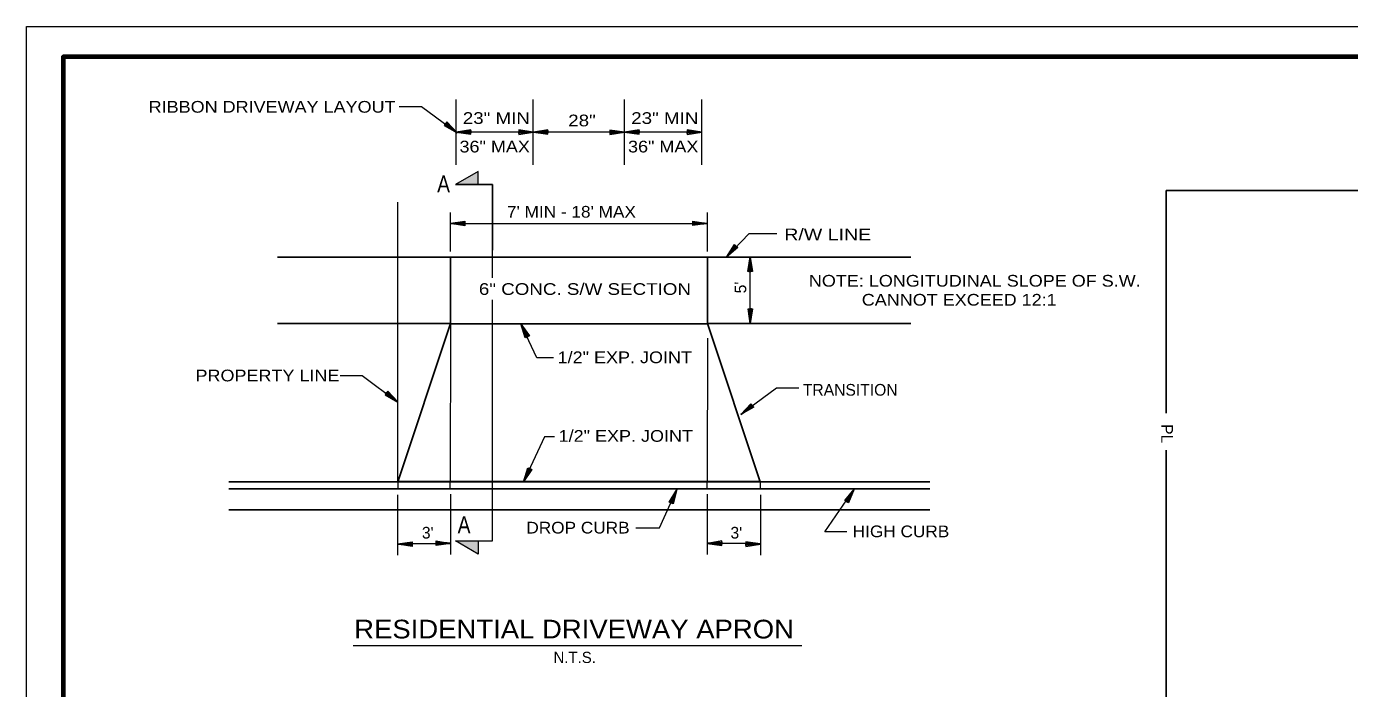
# Model space of a CAD drawing. Extents: x 124.7 to 141.7, y -6.7 to 4.3.
# Drawn here: x 124.66 to 134.08, y -0.42 to 4.3 of the extents above; entities that cross this region are included whole.
import ezdxf

# ---------------------------------------------------------------- set-up
doc = ezdxf.new("R2010")
doc.units = 0
doc.header["$LTSCALE"] = 0.033
for name, color, linetype, lineweight in [('1', 7, 'Continuous', 13), ('6', 7, 'Continuous', 13), ('60', 7, 'Continuous', 13), ('7', 7, 'Continuous', 13), ('8', 7, 'Continuous', 13)]:
    doc.layers.add(name, color=color, linetype=linetype, lineweight=lineweight)

msp = doc.modelspace()

# ---------------------------------------------------------------- hatches: boundary and pattern name
at = {"layer": '6'}
for points in [[(127.712, 3.17258), (127.87396, 3.17258), (127.87396, 3.26548)], [(127.712, 0.63499), (127.87396, 0.63499), (127.87396, 0.54209)]]:
    msp.add_hatch(color=256, dxfattribs=at).paths.add_polyline_path(points)

# ---------------------------------------------------------------- linework, layer by layer
at = {"layer": '1'}
for p, q in [((127.71735, 3.3141), (127.71735, 3.77832)), ((128.26735, 3.3141), (128.26735, 3.77832)), ((128.91735, 3.3141), (128.91735, 3.77832)), ((129.46735, 3.3141), (129.46735, 3.77832)), ((129.46735, 3.54622), (127.71735, 3.54622)), ((127.30268, 1.06025), (127.30268, 3.04831)), ((127.30128, 1.05608), (127.30128, 1.00608)), ((129.88319, 1.05608), (129.88319, 1.00608))]:
    msp.add_line(p, q, dxfattribs=at)
at = {"layer": '6', "lineweight": 25}
for p, q in [((132.77677, 1.54519), (132.77677, 3.13027)), ((132.77677, 3.13027), (136.71186, 3.13027)), ((126.44573, 2.65608), (127.67721, 2.65608)), ((127.67721, 2.65608), (127.67721, 2.18432)), ((129.50727, 2.18432), (129.50727, 2.65608)), ((126.44573, 2.18432), (127.67721, 2.18432)), ((127.67721, 2.18016), (129.50727, 2.18016)), ((129.50727, 2.18432), (130.95673, 2.18432)), ((132.77677, -2.5979), (132.77677, 1.28283)), ((126.09806, 1.05608), (131.09128, 1.05608)), ((126.09806, 1.00608), (131.09128, 1.00608)), ((126.09806, 0.85608), (131.09128, 0.85608))]:
    msp.add_line(p, q, dxfattribs=at)
at = {"layer": '6'}
for p, q in [((127.67721, 2.69545), (127.67721, 2.97502)), ((129.50727, 2.69545), (129.50727, 2.97502)), ((127.67721, 2.89628), (129.50727, 2.89628)), ((129.81224, 2.18432), (129.81224, 2.65608)), ((127.30268, 1.06025), (129.8818, 1.06025)), ((127.6752, 1.00608), (127.67519, 1.05608)), ((129.50643, 1.00608), (129.50643, 1.05608)), ((127.29968, 0.96297), (127.29968, 0.53424)), ((127.67805, 0.96822), (127.67805, 0.53949)), ((129.50643, 0.96822), (129.50643, 0.53949)), ((129.8848, 0.96297), (129.8848, 0.53424)), ((127.33965, 0.61823), (127.67805, 0.61823)), ((129.84483, 0.61823), (129.50643, 0.61823))]:
    msp.add_line(p, q, dxfattribs=at)
for points in [[(127.31231, 3.72973), (127.46994, 3.72973), (127.72372, 3.54149)], [(127.712, 3.17258), (127.97628, 3.17258), (127.97628, 2.70471)], [(127.97628, 2.50923), (127.97628, 3.17258), (127.712, 3.17258)], [(130.00182, 2.82196), (129.80183, 2.82196), (129.64364, 2.65608)], [(127.712, 0.63499), (127.97628, 0.63499), (127.97628, 2.35086)], [(128.41153, 1.93962), (128.29359, 1.93962), (128.17884, 2.18016)], [(126.89127, 1.81282), (127.0489, 1.81282), (127.30268, 1.62458)], [(130.15782, 1.72359), (130.0002, 1.72359), (129.74642, 1.53535)], [(128.41861, 1.37609), (128.34805, 1.37609), (128.19752, 1.05608)], [(127.712, 0.63499), (127.97628, 0.63499), (127.97628, 1.10286)], [(128.99752, 0.72783), (129.1658, 0.72783), (129.29008, 1.00143)], [(130.50201, 0.70041), (130.34439, 0.70041), (130.5535, 1.00372)]]:
    msp.add_lwpolyline(points, dxfattribs=at)
for points in [[(127.712, 3.17258), (127.87396, 3.17258), (127.87396, 3.26548)], [(127.712, 0.63499), (127.87396, 0.63499), (127.87396, 0.54209)]]:
    msp.add_lwpolyline(points, close=True, dxfattribs=at)
at = {"layer": '6', "lineweight": 25}
msp.add_lwpolyline([(127.67721, 2.65608), (129.50727, 2.65608), (130.95673, 2.65608)], dxfattribs=at)
at = {"layer": '60'}
msp.add_lwpolyline([(141.66697, -6.70846), (124.65648, -6.70846), (124.65648, 4.29833), (141.66697, 4.29833)], close=True, dxfattribs=at)
at = {"layer": '60', "lineweight": 70}
msp.add_lwpolyline([(140.98583, 4.08146), (124.91782, 4.08146), (124.91782, -6.47409), (140.98583, -6.47409)], close=True, dxfattribs=at)
at = {"layer": '7'}
msp.add_line((126.98512, -0.10881), (130.17964, -0.10881), dxfattribs=at)
at = {"layer": '8', "lineweight": 25}
for p, q in [((127.67721, 2.18432), (127.30128, 1.05608)), ((129.50727, 2.18432), (129.88319, 1.05608))]:
    msp.add_line(p, q, dxfattribs=at)
at = {"layer": '8'}
for p, q in [((127.67721, 2.18016), (127.67519, 1.05608)), ((129.5072, 2.07893), (129.50643, 1.05608))]:
    msp.add_line(p, q, dxfattribs=at)
for points in [[(127.72368, 3.542), (127.65216, 3.61857), (127.63196, 3.59345), (127.72374, 3.54149)], [(127.64898, 3.61451), (127.72366, 3.54115), (127.64246, 3.60639), (127.6392, 3.60232), (127.72366, 3.54115), (127.63594, 3.59827), (127.64572, 3.61045), (127.7196, 3.54441)], [(127.82152, 3.5358), (127.71735, 3.54622), (127.82152, 3.54622), (127.82152, 3.55143), (127.71735, 3.54622), (127.82152, 3.55664), (127.82152, 3.54101), (127.72256, 3.54622)], [(127.71787, 3.54554), (127.82159, 3.53065), (127.82159, 3.56289), (127.71751, 3.54591)], [(128.26683, 3.5469), (128.1631, 3.56179), (128.1631, 3.52955), (128.2672, 3.54653)], [(128.16319, 3.55664), (128.26735, 3.54622), (128.16319, 3.54622), (128.16319, 3.54101), (128.26735, 3.54622), (128.16319, 3.5358), (128.16319, 3.55143), (128.26215, 3.54622)], [(128.37152, 3.5358), (128.26735, 3.54622), (128.37152, 3.54622), (128.37152, 3.55143), (128.26735, 3.54622), (128.37152, 3.55664), (128.37152, 3.54101), (128.27256, 3.54622)], [(128.26788, 3.54554), (128.37159, 3.53065), (128.37159, 3.56289), (128.26751, 3.54591)], [(128.91735, 3.54622), (128.81363, 3.56111), (128.81363, 3.52887), (128.91772, 3.54585)], [(128.81371, 3.55596), (128.91788, 3.54554), (128.81371, 3.54554), (128.81371, 3.54033), (128.91788, 3.54554), (128.81371, 3.53512), (128.81371, 3.55075), (128.91267, 3.54554)], [(129.02152, 3.5358), (128.91735, 3.54622), (129.02152, 3.54622), (129.02152, 3.55143), (128.91735, 3.54622), (129.02152, 3.55664), (129.02152, 3.54101), (128.92256, 3.54622)], [(128.91788, 3.54554), (129.02159, 3.53065), (129.02159, 3.56289), (128.91751, 3.54591)], [(129.46683, 3.5469), (129.3631, 3.56179), (129.3631, 3.52955), (129.4672, 3.54653)], [(129.36319, 3.55664), (129.46735, 3.54622), (129.36319, 3.54622), (129.36319, 3.54101), (129.46735, 3.54622), (129.36319, 3.5358), (129.36319, 3.55143), (129.46215, 3.54622)], [(127.78007, 2.90654), (127.67591, 2.89613), (127.78007, 2.89613), (127.78007, 2.89092), (127.67591, 2.89613), (127.78007, 2.88571), (127.78007, 2.90133), (127.68111, 2.89613)], [(127.67643, 2.8968), (127.78015, 2.9117), (127.78015, 2.87946), (127.67606, 2.89644)], [(129.50805, 2.89576), (129.40432, 2.88086), (129.40432, 2.9131), (129.50842, 2.89613)], [(129.50805, 2.89576), (129.40432, 2.88086), (129.40432, 2.9131), (129.50842, 2.89613)], [(129.40441, 2.88602), (129.50857, 2.89644), (129.40441, 2.89644), (129.40441, 2.90165), (129.50857, 2.89644), (129.40441, 2.90685), (129.40441, 2.89123), (129.50336, 2.89644)], [(129.40441, 2.88602), (129.50857, 2.89644), (129.40441, 2.89644), (129.40441, 2.90165), (129.50857, 2.89644), (129.40441, 2.90685), (129.40441, 2.89123), (129.50336, 2.89644)], [(129.64347, 2.65693), (129.7004, 2.74491), (129.7247, 2.72372), (129.6435, 2.65642)], [(129.70423, 2.74146), (129.64364, 2.65609), (129.71208, 2.73461), (129.71601, 2.73119), (129.64364, 2.65609), (129.71994, 2.72777), (129.70816, 2.73803), (129.64705, 2.66002)], [(129.81276, 2.65686), (129.82766, 2.55314), (129.79542, 2.55314), (129.8124, 2.65723)], [(129.8225, 2.55322), (129.81208, 2.65739), (129.81208, 2.55322), (129.80687, 2.55322), (129.81208, 2.65739), (129.80167, 2.55322), (129.81729, 2.55322), (129.81208, 2.65218)], [(129.81172, 2.18354), (129.79682, 2.28726), (129.82906, 2.28726), (129.81208, 2.18318)], [(129.80198, 2.28719), (129.8124, 2.18302), (129.8124, 2.28719), (129.8176, 2.28719), (129.8124, 2.18302), (129.82281, 2.28719), (129.80719, 2.28719), (129.8124, 2.18823)], [(128.23454, 2.09307), (128.17811, 2.18125), (128.22526, 2.08835), (128.22061, 2.086), (128.17811, 2.18125), (128.21597, 2.08365), (128.2299, 2.09072), (128.18047, 2.1766)], [(128.17895, 2.18108), (128.23918, 2.09533), (128.21043, 2.08075), (128.17846, 2.18125)], [(127.30262, 1.62509), (127.2311, 1.70168), (127.21091, 1.67654), (127.30269, 1.62458)], [(127.22793, 1.6976), (127.30261, 1.62424), (127.22141, 1.68948), (127.21815, 1.68543), (127.30261, 1.62424), (127.21489, 1.68136), (127.22467, 1.69354), (127.29855, 1.6275)], [(129.74646, 1.53586), (129.81798, 1.61245), (129.83818, 1.58731), (129.7464, 1.53535)], [(129.82116, 1.60837), (129.74647, 1.53501), (129.82768, 1.60026), (129.83094, 1.5962), (129.74647, 1.53501), (129.8342, 1.59214), (129.82442, 1.60432), (129.75053, 1.53828)], [(128.19712, 1.05683), (128.2278, 1.15703), (128.25697, 1.14331), (128.1973, 1.05635)], [(128.23244, 1.15477), (128.19752, 1.05607), (128.24185, 1.15033), (128.24657, 1.14811), (128.19752, 1.05607), (128.25128, 1.14591), (128.23715, 1.15255), (128.19974, 1.06079)], [(129.2905, 1.00069), (129.26457, 0.89916), (129.23478, 0.9115), (129.29031, 1.00117)], [(129.25983, 0.90121), (129.29008, 1.00143), (129.25021, 0.9052), (129.2454, 0.90719), (129.29008, 1.00143), (129.24059, 0.90918), (129.25502, 0.9032), (129.28808, 0.99661)], [(130.55381, 1.00293), (130.51372, 0.90611), (130.48599, 0.92255), (130.55369, 1.00343)], [(130.50932, 0.9088), (130.55349, 1.00372), (130.50036, 0.91411), (130.49589, 0.91677), (130.55349, 1.00372), (130.49141, 0.91943), (130.50484, 0.91146), (130.55083, 0.99924)], [(127.40384, 0.6234), (127.29968, 0.61298), (127.40384, 0.61298), (127.40384, 0.60777), (127.29968, 0.61298), (127.40384, 0.60256), (127.40384, 0.61819), (127.30489, 0.61298)], [(127.3002, 0.61366), (127.40392, 0.62855), (127.40392, 0.59631), (127.29983, 0.61329)], [(127.67883, 0.61771), (127.5751, 0.60281), (127.5751, 0.63505), (127.6792, 0.61807)], [(127.57519, 0.60797), (127.67935, 0.61839), (127.57519, 0.61839), (127.57519, 0.62359), (127.67935, 0.61839), (127.57519, 0.6288), (127.57519, 0.61318), (127.67415, 0.61839)], [(129.60929, 0.60797), (129.50512, 0.61839), (129.60929, 0.61839), (129.60929, 0.62359), (129.50512, 0.61839), (129.60929, 0.6288), (129.60929, 0.61318), (129.51033, 0.61839)], [(129.50565, 0.61771), (129.60936, 0.60281), (129.60936, 0.63505), (129.50528, 0.61807)], [(129.88428, 0.61366), (129.78055, 0.62855), (129.78055, 0.59631), (129.88465, 0.61329)], [(129.78064, 0.6234), (129.8848, 0.61298), (129.78064, 0.61298), (129.78064, 0.60777), (129.8848, 0.61298), (129.78064, 0.60256), (129.78064, 0.61819), (129.87959, 0.61298)]]:
    msp.add_lwpolyline(points, dxfattribs=at)

# ---------------------------------------------------------------- texts
at = {"layer": '6'}
for s, height, width, p in [('RIBBON DRIVEWAY LAYOUT', 0.08333, 1.15, (125.5271, 3.68452)), ('23" MIN', 0.08333, 1.2, (127.76476, 3.60451)), ('23" MIN', 0.08333, 1.2, (128.96476, 3.60451)), ('28"', 0.08333, 1.2, (128.51601, 3.58724)), ('36" MAX', 0.08333, 1.15, (127.74156, 3.40145)), ('36" MAX', 0.08333, 1.15, (128.94211, 3.40145)), ('A', 0.1201, 0.85, (127.5825, 3.11727)), ("7' MIN - 18' MAX", 0.08333, 1.1, (128.07964, 2.9374)), ('R/W LINE', 0.08333, 1.25, (130.05499, 2.77622)), ('6" CONC. S/W SECTION', 0.08333, 1.2, (127.8795, 2.38716)), ('NOTE: LONGITUDINAL SLOPE OF S.W.', 0.08333, 1.15, (130.23032, 2.44594)), ('CANNOT EXCEED 12:1', 0.08333, 1.15, (130.60729, 2.31072)), ('1/2" EXP. JOINT', 0.08333, 1.15, (128.44058, 1.90106)), ('PROPERTY LINE', 0.08333, 1.15, (125.86075, 1.77158)), ('1/2" EXP. JOINT', 0.08333, 1.15, (128.44772, 1.34141)), ('A', 0.1201, 0.85, (127.72851, 0.69042)), ('DROP CURB', 0.08333, 1.1, (128.21786, 0.68826)), ('HIGH CURB', 0.08333, 1.1, (130.54291, 0.66186))]:
    msp.add_text(s, height=height, dxfattribs=dict(at, width=width)).set_placement(p)
for s, rotation, p in [("5'", 90, (129.78444, 2.39812)), ('PL', 270, (132.74046, 1.46698))]:
    msp.add_text(s, height=0.08333, rotation=rotation, dxfattribs=at).set_placement(p)
for s, height, p in [('TRANSITION', 0.08333, (130.18764, 1.66964)), ("3'", 0.08333, (127.47361, 0.65228)), ("3'", 0.08333, (129.67192, 0.65228)), ('N.T.S.', 0.07964, (128.41147, -0.23366))]:
    msp.add_text(s, height=height, dxfattribs=at).set_placement(p)
at = {"layer": '7', "width": 1.1}
msp.add_text('RESIDENTIAL DRIVEWAY APRON', height=0.1331, dxfattribs=at).set_placement((126.99118, -0.05881))

doc.saveas('drawing.dxf')
